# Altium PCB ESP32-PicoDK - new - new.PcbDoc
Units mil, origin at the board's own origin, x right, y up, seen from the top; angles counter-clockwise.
Board outline 1979.37 x 2074.17 mil, 2 copper layers (Top1, Bottom2), stack 40.202 mil thick; 38 components, 64 nets, 219 pads, 89 vias.
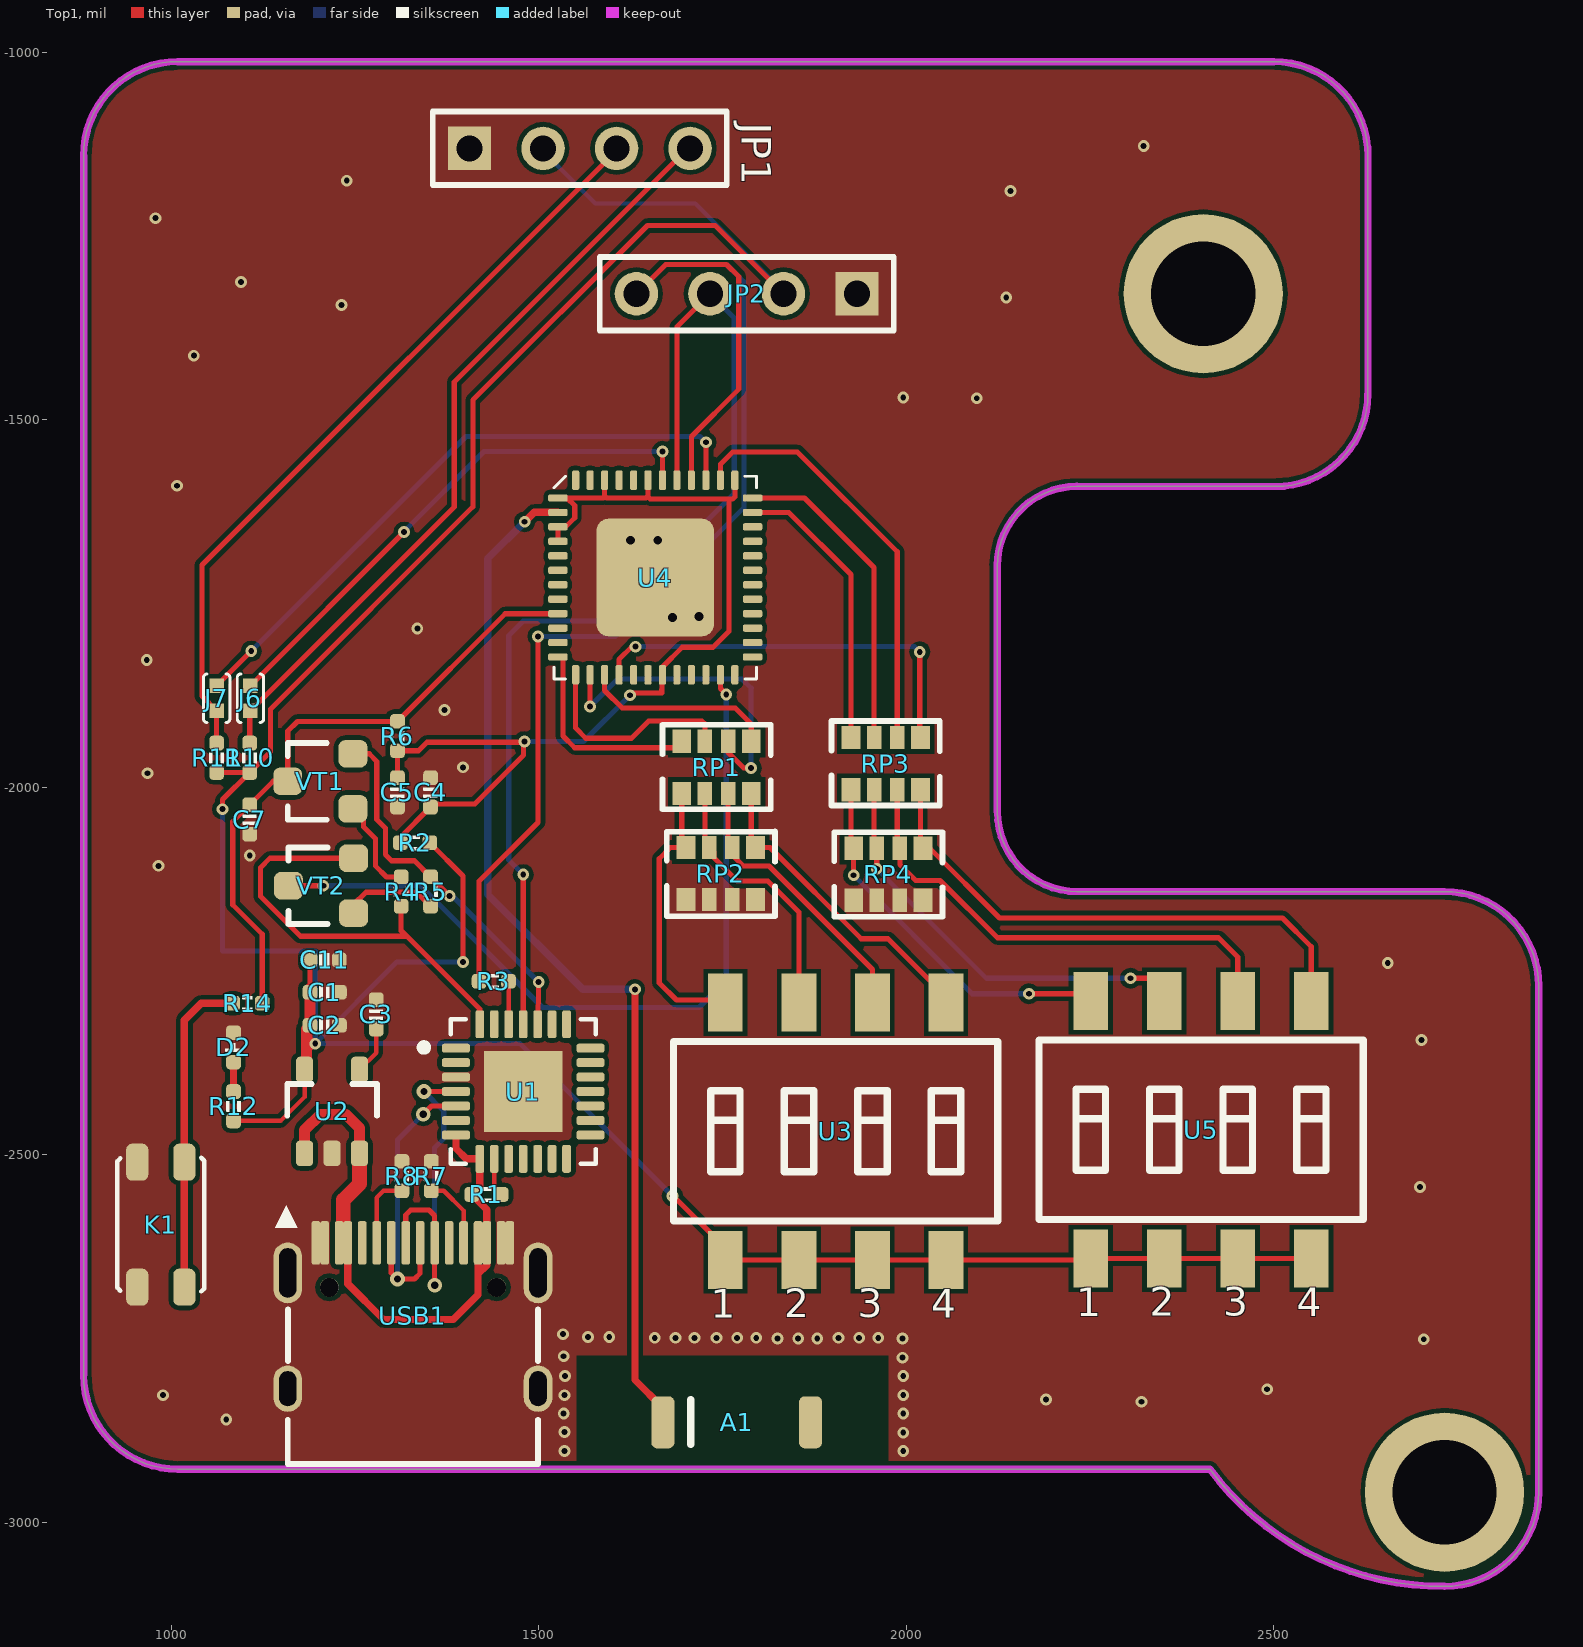
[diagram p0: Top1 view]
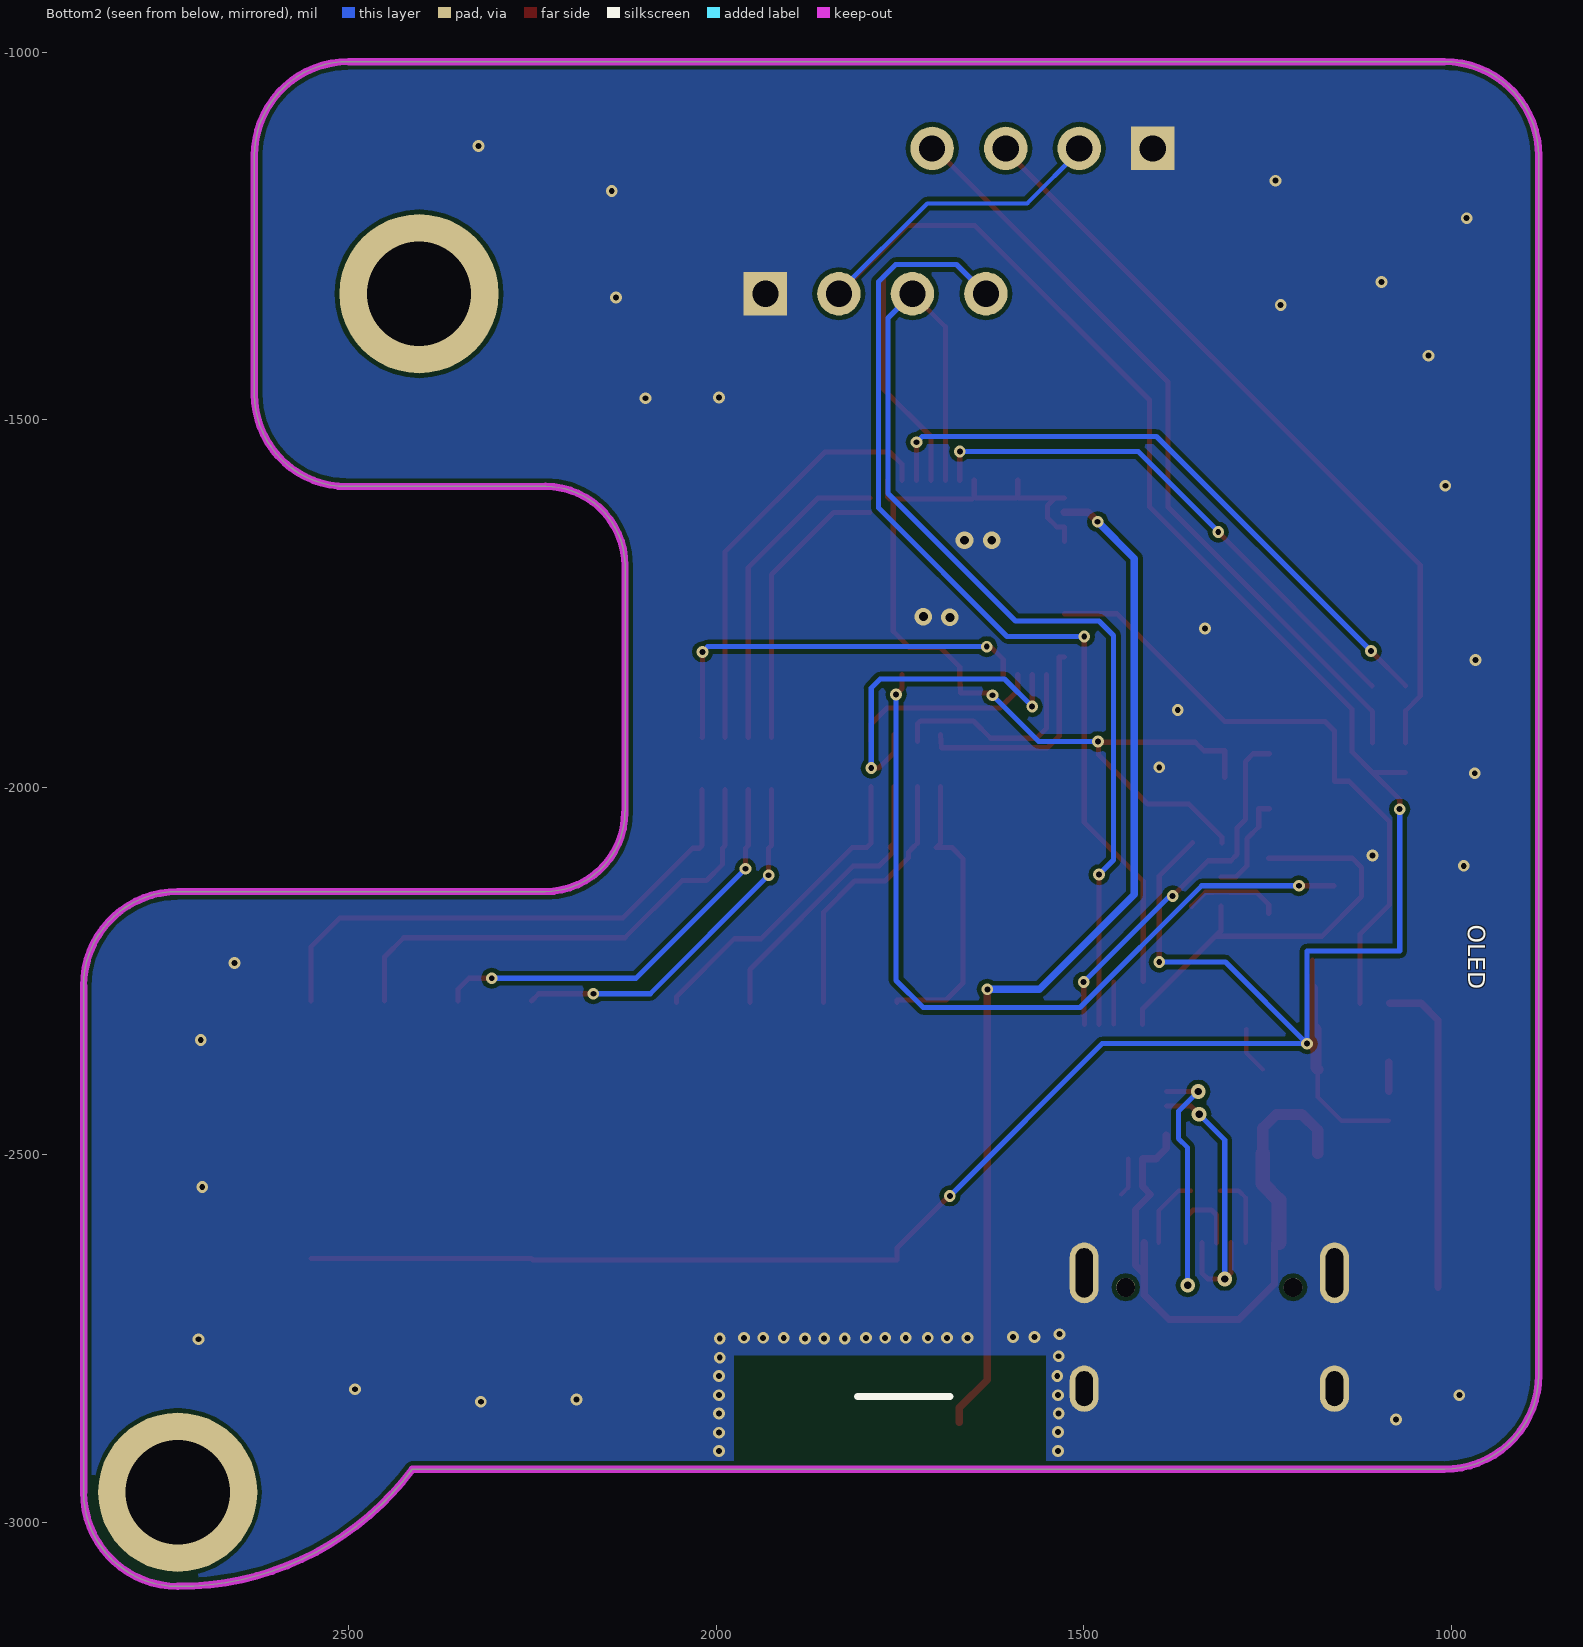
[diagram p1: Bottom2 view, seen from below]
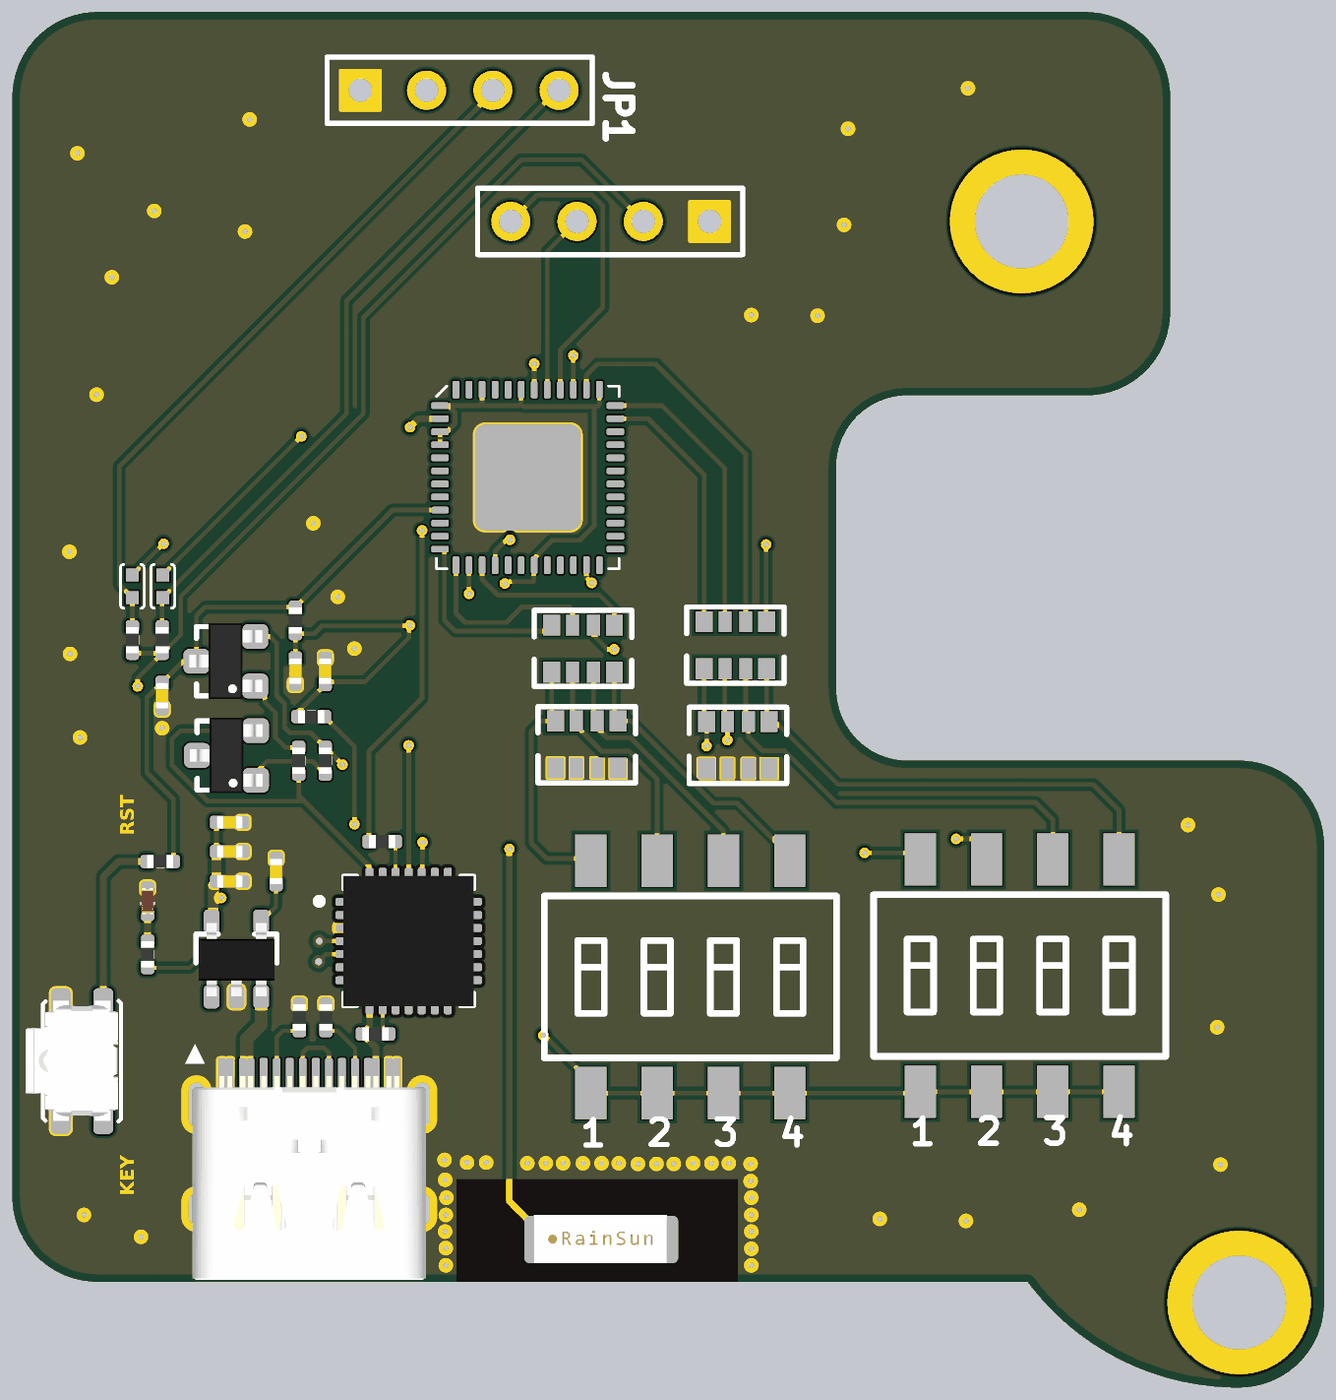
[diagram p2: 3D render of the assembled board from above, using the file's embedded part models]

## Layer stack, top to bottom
Top Solder: solder mask 0.4, Solder Resist, Dk 3.5
Top1: signal copper 1.4
Dielectric 1: core 37.4016, FR-4, Dk 4.2
Bottom2: signal copper 1.4
Bottom Solder: solder mask 0.4, Solder Resist, Dk 3.5

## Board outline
881,-2799.63 ccw(c1009.11,-2799.63) 1009.11,-2927.74 2413.18,-2927.74 ccw(c2730.27,-2692.15) 2732.27,-3087.17 ccw(c2732.26,-2959.06) 2860.37,-2959.06 2860.37,-2270.07 ccw(c2732.26,-2270.07) 2732.26,-2141.96 2232.26,-2141.96 cw(c2232.26,-2033.85) 2124.15,-2033.85 2123.89,-2033.59 2123.89,-1699 cw(c2232,-1699) 2232,-1590.89 2232,-1591 2502.55,-1591 ccw(c2502.55,-1465.55) 2628,-1465.58 2628.11,-1465.55 2628.11,-1141.11 ccw(c2500,-1141.11) 2500,-1013 1009.11,-1013 ccw(c1009.11,-1141.11) 881,-1141.11

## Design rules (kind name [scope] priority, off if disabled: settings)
Clearance [All] p1: gap=6 ignorepadtopadclearanceinfootprint=FALSE
ComponentClearance [All] p1: gap=0 collisioncheckmode=3 verticalgap=0 showdistances=FALSE
DiffPairsRouting [All] p1: maxlimit=9 minlimit=9 mostfreqgap=9 toplayer_minwidth=4 toplayer_maxwidth=4 toplayer_prefwidth=4 bottomlayer_minwidth=4 bottomlayer_maxwidth=4 bottomlayer_prefwidth=4 maxuncoupledlength=500
FanoutControl Fanout_BGA [All] p1: bgadir=Out bgaviamode=Centered fanoutstyle=Auto fanoutdirection=Alternating viagrid=1 // Fanout_BGA (Default Rule)
HoleSize [All] p1: absolutevalues=TRUE maxlimit=10000 minlimit=8 maxpercent=80.000 minpercent=20.000
HoleToHoleClearance [All] p1: gap=0 allowstackedmicrovias=TRUE
MinimumSolderMaskSliver [All] p1 off: minsoldermaskwidth=2
PlaneClearance [All] p1: clearance=8
PlaneConnect [All] p1: planeconnectstyle=Direct reliefexpansion=20 reliefentries=4 reliefconductorwidth=10 reliefairgap=10
PolygonConnect [All] p1: connectstyle=Direct reliefconductorwidth=10 reliefentries=4 polygonreliefangle="90 Angle" airgapwidth=10
RoutingVias [All] p1: holewidth=8 width=16 viastyle="Through Hole" minholewidth=6 minwidth=12 maxholewidth=28 maxwidth=50
SilkToBoardRegionClearance [All] p1 off:
SilkToSilkClearance [All] p1: silktosilkclearance=0
SilkToSolderMaskClearance [IsPad] p1: minsilkscreentomaskgap=0 clearancetoexposedcopper=TRUE
SolderMaskExpansion [All] p1: expansion=3
Width [All] p1: maxlimit=10000 minlimit=6 preferedwidth=7
19 further rules are at their usual default settings.

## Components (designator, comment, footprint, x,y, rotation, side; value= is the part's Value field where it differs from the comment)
A1 "RAINSUN" ANT-Rainsun-AN5120 1769,-2864 r0 top
C1 "0.1uF" CAP_0402 1209,-2279 r180 top value=0.1u
C2 "10uF" CAP_0402 1209,-2324 r180 top value=0.1u
C3 "10nF" CAP_0402 1279,-2309 r270 top value=0.1u
C4 "10uF" CAP_0402 1353,-2007 r270 top value=0.1u
C5 "0.1uF" CAP_0402 1308,-2007 r90 top value=0.1u
C7 "0.1uF" CAP_0402 1107,-2044 r270 top value=0.1u
C11 "10uF" CAP_0402 1208.92,-2235 r180 top value=0.1u
D2 "color?" LED_0402_RED 1085,-2354 r90 top
J6 "跳线" 0402-0R 1108,-1879 r90 top
J7 "跳线" 0402-0R 1062,-1879 r90 top
JP1 "SH_1.0MM_4P" HDR1X4 1406,-1131 r0 top
JP2 "SH_1.0MM_4P" HDR1X4 1933.03,-1328.81 r180 top
K1 "TACT 4P" ButtonTACT_3.5*3.55_90 986,-2595 r90 top value=3.4x3.5
R1 "10K" RES_0402 1429,-2554 r0 top value=22R
R2 "0R" RES_0402 1332,-2075.53 r180 top value=22R
R3 "200R" RES_0402 1439,-2264 r0 top value=22R
R4 "12K" RES_0402 1313,-2142 r90 top value=22R
R5 "12K" RES_0402 1353,-2142 r270 top value=22R
R6 "10K" RES_0402 1308,-1930.5 r90 top value=22R
R7 "5.1K" RES_0402 1354,-2529 r90 top value=22R
R8 "5.1K" RES_0402 1314,-2529 r90 top value=22R
R10 "10K" RES_0402 1107,-1960 r270 top value=22R
R11 "10K" RES_0402 1062,-1960 r270 top value=22R
R12 "1K" RES_0402 1085,-2434 r90 top value=22R
R14 "1K" RES_0402 1104,-2294 r0 top value=22R
RP1 "4D03WGJ0102T5E" RES-ARRAY-SMD_0603-8P-L3.2-W1.6-BL 1742,-1973 r0 top
RP2 "YC164-JR-075K1L" RES-ARRAY-SMD_0603-8P-L3.2-W1.6-BL 1747.76,-2117.57 r180 top
RP3 "4D03WGJ0102T5E" RES-ARRAY-SMD_0603-8P-L3.2-W1.6-BL 1972,-1968 r0 top
RP4 "YC164-JR-075K1L" RES-ARRAY-SMD_0603-8P-L3.2-W1.6-BL 1975.75,-2118.43 r180 top
U1 "CP2102" QFN-28 1479,-2414 r0 top value=Value
U2 "LP2992 3V3" SOT23-5 1219,-2439 r90 top
U3 "DM-04-V" SW-SMD_8P-L11.1-W6.2-P2.54-LS9.8 1904,-2468 r0 top
U4 "ESP32_SIP" QFN-48_7X7 1658.61,-1714.79 r0 top
U5 "DM-04-V" SW-SMD_8P-L11.1-W6.2-P2.54-LS9.8 2401,-2466 r0 top
USB1 "Type-C" Type-C-TOP 1329,-2719 r270 top locked
VT1 "S8050" SMT_TRIODE_NPN 1203,-1992 r90 top
VT2 "S8050" SMT_TRIODE_NPN 1204,-2134.06 r90 top

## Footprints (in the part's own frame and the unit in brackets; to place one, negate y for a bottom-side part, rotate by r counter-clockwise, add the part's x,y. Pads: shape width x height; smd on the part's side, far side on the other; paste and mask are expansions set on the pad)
0402-0R [mm] "选择焊盘"
  rect 0.5x0.5 smd: 1(-0.432,0) 2(0.432,0)
  silkscreen extent -0.84,-0.46 0.84,0.46
ANT-Rainsun-AN5120 [mm] "选择焊盘"
  rrect50% 0.8x1.8 smd: 1(-2.54,0) ""(2.563,0)
  silkscreen extent -1.57,-0.76 -1.57,0.79, body extent -2.57,-0.91 2.54,0.94, height 1.32
ButtonTACT_3.5*3.55_90 [mil]
  rrect50% 50x30 smd: 1(-85,32) 2(-85,-32) 3(85,32) 4(85,-32)
  silkscreen extent -91,-59 91,59, body extent -90,-55 91,85, height 56
CAP_0402 [mil]
  rrect50% 20x20 smd: 1(-20,0) 2(20,0)
  silkscreen extent -7,-9 7,9, body extent -20,-10 20,10, height 20
HDR1X4 [mm] "Connector; Header; 4 Position"
  rect 1.5x1.5 hole 0.9: 1(0,0)
  round 1.5 hole 0.9: 2(2.54,0) 3(5.08,0) 4(7.62,0)
  silkscreen extent -1.27,-1.27 8.89,1.27
LED_0402_RED [mil]
  rrect50% 20x20 smd: 1(-20,0) 2(20,0)
  silkscreen extent -6,-11 6,10, body extent -20,-10 20,10, height 18
QFN-28 [mil]
  rrect50% 38x12 smd mask+5: 1(-91.5,59.06) 2(-91.5,39.37) 3(-91.5,19.69) 4(-91.5,0) 5(-91.5,-19.68) 6(-91.5,-39.37) 7(-91.5,-59.05) 15(91.5,-59.05) 16(91.5,-39.37) 17(91.5,-19.68) 18(91.5,0) 19(91.5,19.69) 20(91.5,39.37) 21(91.5,59.06)
  rrect50% 12x38 smd mask+5: 8(-59.06,-91.5) 9(-39.37,-91.5) 10(-19.69,-91.5) 11(0,-91.5) 12(19.68,-91.5) 13(39.37,-91.5) 14(59.05,-91.5) 22(59.05,91.5) 23(39.37,91.5) 24(19.68,91.5) 25(0,91.5) 26(-19.69,91.5) 27(-39.37,91.5) 28(-59.06,91.5)
  rect 106.3x110.24 smd: 29(0,0)
  silkscreen extent -140,-98 99,99, body extent -98,-98 98,98, height 35
QFN-48_7X7 [mm]
  rrect50% 0.675x0.25 smd: 1(-3.362,2.75) 2(-3.362,2.25) 3(-3.362,1.75) 4(-3.362,1.25) 5(-3.362,0.75) 6(-3.362,0.25) 7(-3.362,-0.25) 8(-3.362,-0.75) 9(-3.362,-1.25) 10(-3.362,-1.75) 11(-3.362,-2.25) 12(-3.362,-2.75) 25(3.363,-2.75) 26(3.363,-2.25) 27(3.363,-1.75) 28(3.363,-1.25) 29(3.363,-0.75) 30(3.363,-0.25) 31(3.363,0.25) 32(3.363,0.75) 33(3.363,1.25) 34(3.363,1.75) 35(3.363,2.25) 36(3.363,2.75)
  rrect50% 0.25x0.675 smd: 13(-2.75,-3.362) 14(-2.25,-3.362) 15(-1.75,-3.362) 16(-1.25,-3.362) 17(-0.75,-3.362) 18(-0.25,-3.362) 19(0.25,-3.362) 20(0.75,-3.362) 21(1.25,-3.362) 22(1.75,-3.362) 23(2.25,-3.362) 24(2.75,-3.362) 37(2.75,3.363) 38(2.25,3.363) 39(1.75,3.363) 40(1.25,3.363) 41(0.75,3.363) 42(0.25,3.363) 43(-0.25,3.363) 44(-0.75,3.363) 45(-1.25,3.363) 46(-1.75,3.363) 47(-2.25,3.363) 48(-2.75,3.363)
  rrect20% 4.064x4.064 smd: 49(0,0)
  silkscreen extent -3.5,-3.5 3.5,3.5, body extent -3.5,-3.5 3.5,3.5, height 1
RES-ARRAY-SMD_0603-8P-L3.2-W1.6-BL [mm]
  rect 0.65x0.8 smd paste+0 mask+0.051: 1(-1.2,-0.9) 4(1.2,-0.9) 5(1.2,0.9) 8(-1.2,0.9)
  rect 0.5x0.8 smd paste+0 mask+0.051: 2(-0.4,-0.9) 3(0.4,-0.9) 6(0.4,0.9) 7(-0.4,0.9)
  silkscreen extent -1.87,-1.45 1.87,1.47
RES_0402 [mil]
  rrect50% 20x20 smd: 1(-20,0) 2(20,0)
  silkscreen extent -6,-10 7,10, body extent -20,-10 20,10, height 14
SMT_TRIODE_NPN [mm] "Surface mount NPN transistor, package SOT-23"
  rrect50% 0.95x1 smd: 1(-0.95,-1.125) 2(0.95,-1.125) 3(0,1.125)
  silkscreen extent -1.33,-0.23 1.33,1.12, body extent -1.45,-1.4 1.45,1.4, height 1.3
SOT23-5 [mm] "SOT23, 3-Leads, Body 3.1x3.0mm (max), Pitch 0.95mm, IPC Medium Density"
  rrect50% 0.889x0.6 smd: 1(-1.5,0.95) 2(-1.5,0) 3(-1.5,-0.95) 4(1.396,-0.95) 5(1.396,0.95)
  silkscreen extent -0.2,-1.55 0.9,1.55, body extent -1.48,-1.45 1.32,1.45, height 1.2
SW-SMD_8P-L11.1-W6.2-P2.54-LS9.8 [mm]
  rect 1.2x2 smd paste+0 mask+0.051: 1(-3.81,-4.45) 2(-1.27,-4.45) 3(1.27,-4.45) 4(3.81,-4.45) 5(3.81,4.45) 6(1.27,4.45) 7(-1.27,4.45) 8(-3.81,4.45)
  silkscreen extent -5.6,-3.1 5.6,3.1
Type-C-TOP [mm]
  round 0.65 hole 0.65: 0(-0.98,2.89) 0(-0.98,-2.89)
  oval 1.6x1 hole 0.6 slot 1.2 at 0 deg: 1(2.52,4.325) 2(2.52,-4.325)
  oval 2.1x1 hole 0.6 slot 1.7 at 0 deg: 3(-1.48,-4.325) 4(-1.48,4.325)
  rrect50% 1.5x0.3 smd: A1(-2.52,-3.35) A4(-2.52,-2.55) A5(-2.52,-1.25) A6(-2.52,-0.25) A7(-2.52,0.25) A8(-2.52,1.25) A9(-2.52,2.55) A12(-2.52,3.35) B1(-2.52,3.05) B4(-2.52,2.25) B5(-2.52,1.75) B6(-2.52,0.75) B7(-2.52,-0.75) B8(-2.52,-1.75) B9(-2.52,-2.25) B12(-2.52,-3.05)
  silkscreen extent -0.22,-4.32 5.12,4.32, body extent -2.57,-4.48 5.18,4.48, height 3.26

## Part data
A1: library part ANT-Rainsun-AP5120
C1 C2 C3 C4 C5 C7 C11: library part 电容-0402, "Capacitor"
D2: library part LED_0402, "LED"
J6 J7: "Resistor"
K1: library part ButtonTACT, "Button"
R1 R2 R3 R4 R5 R6 R7 R8 R10 R11 R12 R14: library part 电阻-0402, "Resistor"
RP1 RP2 RP3 RP4: library part RP
U1: "USBתTTL"
U2: library part LP2992, "LDO"
U3 U5: library part "SW DIP-4", "DIP Switch, 4 Position, SPST"
U4: library part ESP32-PICO
USB1: library part USB-Type-C-TOP
VT1 VT2: library part SMT_TRIODE_NPN, "Surface mount NPN transistor, package SOT-23"

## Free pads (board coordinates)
  round 216.54 hole 141.73 mask+4: 6(2404.04,-1328.81) 6(2732.26,-2959.06)

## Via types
v1: diameter 16, hole 8, Top1 to Bottom2, 81 vias
v2: diameter 24, hole 12, Top1 to Bottom2, 4 vias
v3: diameter 20, hole 10, Top1 to Bottom2, tented both sides, 4 vias

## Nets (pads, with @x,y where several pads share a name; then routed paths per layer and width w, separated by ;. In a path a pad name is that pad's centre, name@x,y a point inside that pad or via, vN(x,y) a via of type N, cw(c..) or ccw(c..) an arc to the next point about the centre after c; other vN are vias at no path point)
3V3A: C4.2 C5.2 R2.2 R6.1 U4.1 U4.3 U4.4 U4.19 U4.37 U4.43 U4.46 | length 1383.8
  Top1 w7: C5.2 R6.1@1308,-1953.01 ; R6.1 1336.5,-1950.5 1348.11,-1938.89 v1@1479.62,-1938.89 ; R2.2 1312,-2068 C4.2 1357,-2023 1413,-2023 1479.62,-1956.38 v1@1479.62,-1938.89 ; v1(1480.63,-1937.88) v1@1479.62,-1938.89 ; U4.4 U4.3 1536.75,-1645.89 1549.02,-1633.62 1549.02,-1617.01 U4.1@1538.53,-1606.52 ; U4.1 U4.1@1538.53,-1606.52 ; U4.46 1589.72,-1603.97 ; v1(1624.13,-1874.88) 1627.13,-1871.88 1667.46,-1871.88 U4.19 1668.46,-1836.65 1695.42,-1809.69 1737.31,-1809.69 1759,-1788 1759,-1608.88 1758,-1607.88 ; U4.43 1648.77,-1603.88 ; U4.37 1766.88,-1604.88 1763.88,-1607.88 1758,-1607.88 ; U4.1@1538.53,-1606.52 1588.13,-1606.52 1589.72,-1604.93 1589.72,-1603.97 ; 1589.72,-1603.97 1592.27,-1606.52 1646.13,-1606.52 1648.77,-1603.88 ; 1648.77,-1603.88 1648.77,-1604.88 1651.77,-1607.88 1758,-1607.88
  Bottom2 w7: v1(1480.63,-1937.88) 1561.13,-1937.88 v1(1624.13,-1874.88)
CP_Rx: JP2.3 U1.25 U4.41 | length 1481.3
  Top1 w7: U1.25 v1(1479,-2118.88) ; U4.41 1688.14,-1373.69 JP2.3
  Bottom2 w7: v1(1479,-2118.88) 1459.31,-2099.19 1459.31,-1793.68 1479.12,-1773.88 1592.59,-1773.88 1766.13,-1600.35 1766.13,-1361.91 JP2.3
CP_Tx: JP2.4 R3.1 U4.40 | length 1800.8
  Top1 w7: R3.1 1419,-2128.01 1499.13,-2047.88 v1(1499.13,-1794.88) ; JP2.4 1672.96,-1288.88 1755.63,-1288.88 1772.13,-1305.38 1772.13,-1458.58 1707.83,-1522.88 U4.40
  Bottom2 w7: v1(1499.13,-1794.88) 1604.13,-1794.88 1779.13,-1619.88 1779.13,-1312.38 1755.63,-1288.88 1672.96,-1288.88 JP2.4
DTR: R4.1 U1.28 VT2.2 | length 607.4
  Top1 w7: VT2.2 1134.38,-2096.66 1121.88,-2109.16 1121.88,-2148.87 1175.88,-2202.87 1320,-2202.87 1313,-2195.87 1313,-2194.93 ; R4.1 1313,-2194.93 ; U1.28 1419.94,-2301.87 1313,-2194.93
EN: C7.1 R6.2 R14.2 U4.9 VT1.3 | length 863.2
  Top1 w7: R14.2 1124,-2199.99 1083.88,-2159.87 1083.88,-2047.12 C7.1 1139,-1992 VT1.3 1158.71,-1923.67 1171.88,-1910.5 R6.2 1454.5,-1764 U4.9
FLASH_CLK: U4.31
FLASH_CS: U4.25
FLASH_SD0: U4.27
FLASH_SD1: U4.33
FLASH_SD2: U4.30
FLASH_SD3: U4.32
GND: C1.1 C2.1 C3.1 C4.1 C5.1 C7.2 C11.1 D2.2 JP1.1 JP2.1 K1.1 K1.3 R7.2 R8.2 RP2.5 RP2.6 RP2.7 RP2.8 RP4.5 RP4.6 RP4.7 RP4.8 U1.3 U1.29 U2.2 U4.49 USB1.1 USB1.2 USB1.3 USB1.4 USB1.A1 USB1.A12 USB1.B1 USB1.B12
  other v1: 1535,-2903 1996,-2903 1996,-2878 1535,-2877 1075,-2860 1534,-2852 1996,-2852 2320,-2836 2190,-2833 989,-2827 1535,-2827 1996,-2827 2491,-2819 1536,-2801 1996,-2801 1995,-2776 1534,-2774 2704,-2751 1825,-2750 1853,-2750 1879,-2750 1995,-2750 1658,-2749 1686,-2749 1712,-2749 1742,-2749 1770,-2749 1796,-2749 1908,-2749 1936,-2749 1962,-2749 1567,-2748 1596,-2748 1533,-2744 2699,-2544 2701,-2344 2655,-2239 983,-2107 1107,-2093 968,-1981 1397.13,-1973 1372,-1895 967,-1827 1335,-1784 1008,-1590 2096,-1471 1996,-1470 1031,-1413 1232,-1344 2136,-1334 1095,-1313 979,-1226 2142,-1189 1239,-1175 2323,-1128
  other v2: 1682,-1769 1718,-1768 1625,-1664 1662,-1664
GPIO0: U4.23 VT2.3 | length 1098.4
  Top1 w7: VT2.3 v1(1207.13,-2134.06) ; U4.23 1747.2,-1865.95 v1(1755.13,-1873.88)
  Bottom2 w7: v1(1207.13,-2134.06) 1339.31,-2134.06 1505.13,-2299.88 1718.12,-2299.88 1755.13,-2262.87 v1(1755.13,-1873.88)
GPIO2: U4.22
GPIO4: U4.24
GPIO5: U4.34
GPIO9: U4.28
GPIO10: U4.29
GPIO12: U4.18
GPIO13: U4.20
GPIO14: U4.17
GPIO15: U4.21
GPIO18: RP3.8 U4.35 | length 390.6
  Top1 w7: U4.35 1840.2,-1626.2 1924.76,-1710.76 RP3.8
GPIO19: RP3.6 U4.38 | length 578.3
  Top1 w7: U4.38 1747.2,-1560.81 1764.13,-1543.88 1851.88,-1543.88 1987.75,-1679.75 RP3.6
GPIO21: J6.2 U4.42 | length 733.5
  Top1 w7: J6.2 v1(1317,-1653) ; U4.42 v1(1668.46,-1543.38)
  Bottom2 w7: v1(1317,-1653) 1316,-1653 1316.5,-1652.5 1425.62,-1543.38 v1(1668.46,-1543.38)
GPIO22: J7.2 U4.39 | length 860.7
  Top1 w7: J7.2 v1(1109.13,-1814.88) ; U4.39 v1(1727.51,-1530.88)
  Bottom2 w7: v1(1109.13,-1814.88) 1401.01,-1523 1719.63,-1523 v1(1727.51,-1530.88)
GPIO23: RP3.7 U4.36 | length 435.8
  Top1 w7: U4.36 1861.52,-1606.52 1956.25,-1701.25 RP3.7
GPIO25: RP1.6 U4.14 | length 455.9
  Top1 w7: v1(1570.03,-1890.34) U4.14 ; RP1.6@1757.75,-1928.57 RP1.6 1757.75,-1952.88 1778.87,-1974 v1(1789,-1974)
  Bottom2 w7: v1(1570.03,-1890.34) 1607.49,-1852.88 1776.63,-1852.88 1789.13,-1865.38 1789,-1865.51 v1(1789,-1974)
GPIO26: RP1.5 U4.15 | length 263.1
  Top1 w7: U4.15 1589.72,-1868.47 1613.63,-1892.38 1767.38,-1892.38 1789.24,-1914.24 1789.24,-1928.57 RP1.5
GPIO27: RP3.5 U4.16 | length 557
  Top1 w7: U4.16 1609.4,-1826.1 1626.63,-1808.88 v1(1631.88,-1808.88) ; v1(2018.36,-1816) 2018.36,-1931.68 RP3.5
  Bottom2 w7: v1(1631.88,-1808.88) 2011.24,-1808.88 v1(2018.36,-1816)
GPIO32: RP1.8 U4.12 | length 298.9
  Top1 w7: U4.12 1533.13,-1823.05 1533.13,-1930.38 1549.13,-1946.38 1693.26,-1946.38 1694.01,-1937.5 RP1.8@1694.76,-1928.57
GPIO33: RP1.7 U4.13 | length 288.8
  Top1 w7: U4.13 1550.35,-1919.6 1564.13,-1933.38 1626.49,-1933.38 1649.87,-1910 1722,-1910 1726.25,-1914.25 1726.25,-1928.57 RP1.7
GPIO34: U4.10
GPIO35: U4.11
GPIO37: U4.6
GPIO38: U4.7
NetA1_1: A1.1 U4.2 | length 1436.4
  Top1 w10: v1(1481,-1639) 1493.8,-1626.2 U4.2 ; v1(1631,-2275) 1631,-2806.31 1669,-2844.31 A1.1
  Bottom2 w10: v1(1481,-1639) 1431,-1689 1431,-2146 1560,-2275 v1(1631,-2275)
NetC3_2: C3.2 U2.4 | length 64.4
  Top1 w6: U2.4 1279,-2361.46 C3.2
NetD1_1: 
NetD2_1: D2.1 R12.2 | length 40
  Top1 w10: R12.2 D2.1
NetK1_2: K1.2 K1.4 R14.1 | length 438.5
  Top1 w10: K1.2 K1.4 1018,-2317 1041,-2294 R14.1
NetR1_2: R1.2 U1.9 | length 52.4
  Top1 w6: U1.9 1439.63,-2544.63 R1.2
NetR3_2: R3.2 U1.26 | length 58.2
  Top1 w6: U1.26 R3.2@1459.31,-2264.31
NetR4_2: R4.2 VT1.1 | length 140.1
  Top1 w7: VT1.1 1261.88,-2029.4 1261.88,-2053.87 1277.88,-2069.87 1277.88,-2106.87 1293.01,-2122 R4.2
NetR5_2: R5.2 VT2.1 | length 131.7
  Top1 w7: VT2.1 1248.29,-2159.62 1265.04,-2142.87 1301.62,-2142.87 1301.99,-2142.5 1324.01,-2142.5 1324.38,-2142.87 1333.87,-2142.87 R5.2
NetR7_1: R7.1 USB1.B5 | length 98.9
  Top1 w6: R7.1 1371,-2549 1397.9,-2575.9 USB1.B5
NetR8_1: R8.1 USB1.A5 | length 99.6
  Top1 w6: USB1.A5 1279.79,-2558.21 1289,-2549 R8.1
NetRP1_1: RP1.1 RP2.4 U3.8 | length 399.7
  Top1 w7: RP1.1@1694.76,-1999.44 RP1.1 1694.76,-2076.37 RP2.4 1679.13,-2082.13 1664,-2097.26 1664,-2266.25 1687.39,-2289.64 1754,-2289.64 U3.8
NetRP1_2: RP1.2 RP2.3 U3.7 | length 370.7
  Top1 w7: RP1.2@1726.25,-1999.44 RP1.2 1726.25,-2076.37 RP2.3 1738.35,-2088.47 1738.35,-2096 1770.11,-2127.75 1811.73,-2127.75 1854,-2170.02 U3.7
NetRP1_3: RP1.3 RP2.2 U3.6 | length 400.2
  Top1 w7: RP1.3@1757.75,-1999.44 RP1.3 1757.75,-2076.37 RP2.2@1760,-2078.62 ; RP2.2 RP2.2@1760,-2078.62 ; U3.6 1954,-2248 1813.38,-2107.38 1778.27,-2107.38 1760,-2089.11 RP2.2@1760,-2078.62
NetRP1_4: RP1.4 RP2.1 U3.5 | length 435.9
  Top1 w7: RP1.4@1789.24,-1999.44 RP1.4 1789.24,-2076.37 RP2.1 1814.79,-2082.13 1938.84,-2206.17 1975.17,-2206.17 2054,-2285 U3.5
NetRP3_1: RP3.1 RP4.4 U5.8 | length 511.3
  Top1 w7: RP3.1 1924.76,-2079.25 RP4.4 v1(1928.51,-2119.88) ; v1(2167,-2281) 2241.19,-2281 U5.8
  Bottom2 w7: v1(1928.51,-2119.88) 2089.63,-2281 v1(2167,-2281)
NetRP3_2: RP3.2 RP4.3 U5.7 | length 583.9
  Top1 w7: RP3.2 1956.25,-2079.25 RP4.3 v1(1960,-2110.88) ; v1(2305.13,-2259.88) 2336,-2259.88 2351,-2274.88 U5.7
  Bottom2 w7: v1(1960,-2110.88) 2109,-2259.88 v1(2305.13,-2259.88)
NetRP3_3: RP3.3 RP4.2 U5.6 | length 674.8
  Top1 w7: RP3.3 1987.75,-2079.25 RP4.2 1991.5,-2105.38 2013,-2126.88 2046.13,-2126.88 2124.13,-2204.88 2424.88,-2204.88 2451,-2231 U5.6
NetRP3_4: RP3.4 RP4.1 U5.5 | length 738.4
  Top1 w7: RP3.4 2019.24,-2079.25 RP4.1 2032,-2083 2126.88,-2177.88 2511.88,-2177.88 2551,-2217 U5.5
OLED_SCL: J7.1 JP1.3 R11.1 | length 1053.5
  Top1 w7: R11.1 J7.1 1042.13,-1876.13 1042.13,-1697.87 1607.5,-1132.5 JP1.3@1610,-1130
OLED_SDA: J6.1 JP1.4 R10.1 | length 1058.9
  Top1 w7: R10.1 1107,-1897 J6.1 1385.13,-1618.87 1385.13,-1448.87 1658.12,-1175.88 1703,-1131 JP1.4
RTS: R5.1 U1.24 VT1.2 | length 506.2
  Top1 w7: VT1.2 1269.6,-1954.6 1279.88,-1964.88 1279.88,-2043.87 1291.47,-2055.46 1291.47,-2091.47 1300,-2100 1331,-2100 R5.1 v1(1378.91,-2147.91) ; U1.24 1499.8,-2286.2 1499.8,-2265.2 v1(1500,-2265)
  Bottom2 w7: v1(1378.91,-2147.91) 1382.91,-2147.91 v1(1500,-2265)
SENSOR_VN: U4.8
SENSOR_VP: U4.5
USB-PWR-DM: U1.5 USB1.A7 USB1.B7 | length 415.9
  Top1 w7: USB1.B7 1299.47,-2660.47 v3(1308,-2669) 1331,-2669 1338.84,-2661.16 USB1.A7 ; v3(1343,-2445) 1354.31,-2433.68 U1.5
  Bottom2 w7: v3(1308,-2669) 1308,-2480 v3(1343,-2445)
USB-PWR-DP: U1.4 USB1.A6 USB1.B6 | length 501.5
  Top1 w7: USB1.A6 1319.16,-2581.84 1326,-2575 1351,-2575 1358.53,-2582.53 USB1.B6 v3(1358.53,-2677.47) ; v3(1344,-2414) U1.4
  Bottom2 w7: v3(1344,-2414) 1370.91,-2440.91 1370.91,-2478.09 1358.53,-2490.47 v3(1358.53,-2677.47)
VBUS: R1.1 U1.7 U1.8 U2.1 U2.3 USB1.A4 USB1.A9 USB1.B4 USB1.B9 | length 868.8
  Top1 w7: USB1.A4 1234.42,-2619.79 USB1.B9
  Top1 w10: USB1.B9 1240.42,-2675.42 1289,-2724 1384,-2724 1417.58,-2690.42 1417.58,-2662 ; U1.7 1387.5,-2491.5 1401.5,-2505.5 U1.8 1419.94,-2543.05 R1.1 1429.39,-2574.39 USB1.A9 1429.39,-2650.19 1417.58,-2662 ; USB1.B4 1417.58,-2662
  Top1 w15: U2.1 1181.6,-2466.4 1203,-2445 1238,-2445 1256.4,-2463.4 U2.3
  Top1 w20: USB1.A4@1234.42,-2619.79 1234.42,-2561.58 1256.4,-2539.6 U2.3
VCC_3V3: C1.2 C2.2 C11.2 JP1.2 JP2.2 R2.1 R10.2 R11.2 R12.1 U2.5 U3.1 U3.2 U3.3 U3.4 U5.1 U5.2 U5.3 U5.4 | length 4511.5
  Top1 w6: R12.1 1149,-2454 1181.6,-2421.4 U2.5
  Top1 w7: R11.2 R10.2 ; v1(1070.13,-2029.88) 1070.13,-2016.87 R10.2 ; U2.5 1181.6,-2363.41 1184,-2361.01 v1(1196.13,-2348.88) 1188.92,-2341.67 1188.92,-2324.08 1188.92,-2254.87 ; C11.2 1188.92,-2254.87 ; C1.2@1189,-2274 1189,-2254.95 1188.92,-2254.87 ; R2.1 1397.13,-2120.66 v1(1397.13,-2237.88) ; v1(1682,-2556) 1683.12,-2556 1754,-2626.88 U3.1 U3.2 U3.3 U3.4 2249,-2643.19 U5.1 U5.2 U5.3 U5.4 ; JP2.2 1740.1,-1235.88 1648.13,-1235.88 1410.5,-1473.51 1410.5,-1618.51 1135.13,-1893.88 1135.13,-1951.87 R10.2
  Top1 w15: U2.5 1184,-2381.65 1184,-2361.01 1184,-2329 1188.92,-2324.08 C2.2 C1.2 C1.2@1189,-2274
  Bottom2 w6: JP1.2@1504,-1133 1577,-1206 1712.92,-1206 1833.03,-1326.1 JP2.2
  Bottom2 w7: v1(1070.13,-2029.88) 1070.13,-2222.88 1196.13,-2222.88 v1(1196.13,-2348.88) ; v1(1397.13,-2237.88) 1307.13,-2237.88 v1(1196.13,-2348.88) ; v1(1682,-2556) 1474.88,-2348.88 v1(1196.13,-2348.88)
pads on no net: A1. U1.1 U1.2 U1.6 U1.10 U1.11 U1.12 U1.13 U1.14 U1.15 U1.16 U1.17 U1.18 U1.19 U1.20 U1.21 U1.22 U1.23 U1.27 U4.26 U4.44 U4.45 U4.47 U4.48 USB1.0 USB1.A8 USB1.B8

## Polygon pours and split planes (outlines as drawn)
GND on Top1 "GND_L01_P000" (solid, remove dead copper, pour order 0): 855,-942 855,-3163 2946.08,-3163 2975,-942
GND on Bottom2 "GND_L02_P001" (solid, remove dead copper, pour order 1): 869,-938 869,-3162.98 2989,-3163.02 2989,-938

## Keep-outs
Keep-Out Layer:
  lines w10: 2123.89,-2033.59 2123.89,-1699 cw(c2232,-1699) 2232,-1590.89 ; 2124.15,-2033.85 ccw(c2232.26,-2033.85) 2232.26,-2141.96 2732.26,-2141.96 cw(c2732.26,-2270.07) 2860.37,-2270.07 2860.37,-2959.06 cw(c2732.26,-2959.06) 2732.27,-3087.17 cw(c2730.27,-2692.15) 2413.18,-2927.74 1009.11,-2927.74 cw(c1009.11,-2799.63) 881,-2799.63 881,-1141.11 cw(c1009.11,-1141.11) 1009.11,-1013 2500,-1013 cw(c2500,-1141.11) 2628.11,-1141.11 2628.11,-1465.55 ; 2232,-1591 2502.55,-1591 ccw(c2502.55,-1465.55) 2628,-1465.58

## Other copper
Top1:
  pour cut-out: 1976,-2773 1551,-2773 1551,-2998 1976,-2998
Bottom2:
  pour cut-out: 1976,-2773 1551,-2773 1551,-2998 1976,-2998

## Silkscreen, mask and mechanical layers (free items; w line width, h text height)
Top Overlay:
  region: 1171.5,-2599 1141.5,-2599 1156.5,-2569
Bottom Overlay:
  lines w10: 1682.16,-2828.84 1807.16,-2828.84
  text "OLED" at 985,-2187 h40 r90
Top Solder:
  region: 1551,-2773 1551,-2998 1976,-2998 1976,-2773
  text "RST" at 1092.01,-2262.35 h40 r90
  text "KEY" at 1092.01,-2805.82 h40 r90
Bottom Solder:
  region: 1551,-2773 1551,-2998 1976,-2998 1976,-2773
